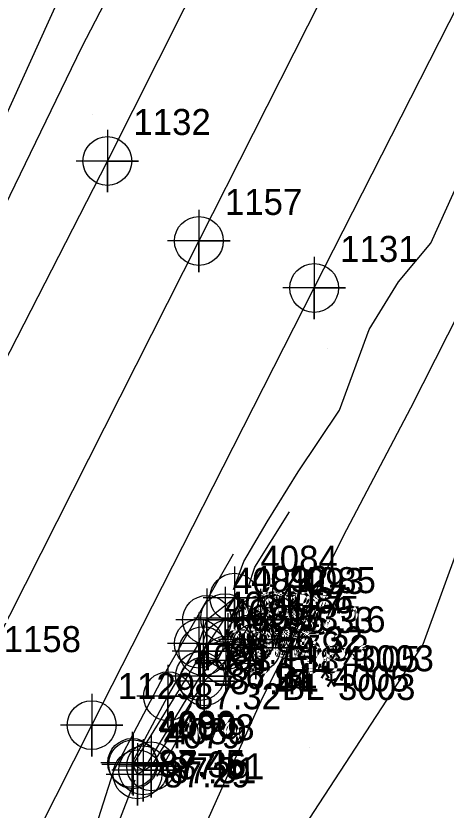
# Model space of a CAD drawing. Extents: x 2062781 to 2066835, y 358981 to 366501.
# Drawn here: x 2064085.2 to 2064126.5, y 361471.1 to 361547.4 of the extents above; entities that cross this region are included whole.
import ezdxf

# ---------------------------------------------------------------- set-up
doc = ezdxf.new("R2010")
doc.units = 0
for name, color, linetype in [('Exist DTM Breakline', 7, 'Continuous'), ('Exist DTM Breakline Cogo Comment', 7, 'Continuous'), ('Exist DTM Breakline Cogo Elevation', 7, 'Continuous'), ('Exist DTM Breakline Cogo Number', 7, 'Continuous'), ('Exist DTM Breakline Cogo Point CELL', 7, 'Continuous'), ('Exist DTM Crownline', 7, 'Continuous'), ('Exist DTM Crownline Cogo Number', 7, 'Continuous'), ('Exist DTM Crownline Cogo Point CELL', 7, 'Continuous'), ('Exist Roads EOP', 7, 'Continuous'), ('Exist Roads EOP Cogo Number', 7, 'Continuous'), ('Exist Roads EOP Cogo Point CELL', 7, 'Continuous'), ('Exist Roads EOP Other', 7, 'Continuous'), ('Exist Roads EOP Other Cogo Comment', 7, 'Continuous'), ('Exist Roads EOP Other Cogo Elevation', 7, 'Continuous'), ('Exist Roads EOP Other Cogo Number', 7, 'Continuous'), ('Exist Roads EOP Other Cogo Point CELL', 7, 'Continuous'), ('PH Exist DTM Breakline', 7, 'Continuous'), ('PH Exist DTM Point', 7, 'Continuous')]:
    doc.layers.add(name, color=color, linetype=linetype)

msp = doc.modelspace()

# ---------------------------------------------------------------- linework, layer by layer
at = {"layer": 'Exist DTM Breakline'}
msp.add_lwpolyline([(2064107.664, 361487.481), (2064105.549, 361487.003), (2064102.879, 361483.967), (2064097.416, 361474.92), (2064096.448, 361475.487), (2064103.189, 361486.361), (2064105.283, 361489.536), (2064108.699, 361489.355)], dxfattribs=at)
at = {"layer": 'Exist DTM Breakline Cogo Point CELL'}
for points in [[(2064105.283, 361492.536), (2064105.283, 361486.536), (2064105.283, 361489.536), (2064108.283, 361489.536), (2064102.283, 361489.536)], [(2064105.283, 361492.536), (2064105.283, 361486.536), (2064105.283, 361489.536), (2064108.283, 361489.536), (2064102.283, 361489.536)], [(2064105.283, 361492.536), (2064105.283, 361486.536), (2064105.283, 361489.536), (2064108.283, 361489.536), (2064102.283, 361489.536)], [(2064108.699, 361492.355), (2064108.699, 361486.355), (2064108.699, 361489.355), (2064111.699, 361489.355), (2064105.699, 361489.355)], [(2064108.699, 361492.355), (2064108.699, 361486.355), (2064108.699, 361489.355), (2064111.699, 361489.355), (2064105.699, 361489.355)], [(2064108.699, 361492.355), (2064108.699, 361486.355), (2064108.699, 361489.355), (2064111.699, 361489.355), (2064105.699, 361489.355)], [(2064105.549, 361490.003), (2064105.549, 361484.003), (2064105.549, 361487.003), (2064108.549, 361487.003), (2064102.549, 361487.003)], [(2064105.549, 361490.003), (2064105.549, 361484.003), (2064105.549, 361487.003), (2064108.549, 361487.003), (2064102.549, 361487.003)], [(2064105.549, 361490.003), (2064105.549, 361484.003), (2064105.549, 361487.003), (2064108.549, 361487.003), (2064102.549, 361487.003)], [(2064107.664, 361490.481), (2064107.664, 361484.481), (2064107.664, 361487.481), (2064110.664, 361487.481), (2064104.664, 361487.481)], [(2064107.664, 361490.481), (2064107.664, 361484.481), (2064107.664, 361487.481), (2064110.664, 361487.481), (2064104.664, 361487.481)], [(2064107.664, 361490.481), (2064107.664, 361484.481), (2064107.664, 361487.481), (2064110.664, 361487.481), (2064104.664, 361487.481)], [(2064103.189, 361489.361), (2064103.189, 361483.361), (2064103.189, 361486.361), (2064106.189, 361486.361), (2064100.189, 361486.361)], [(2064103.189, 361489.361), (2064103.189, 361483.361), (2064103.189, 361486.361), (2064106.189, 361486.361), (2064100.189, 361486.361)], [(2064103.189, 361489.361), (2064103.189, 361483.361), (2064103.189, 361486.361), (2064106.189, 361486.361), (2064100.189, 361486.361)], [(2064102.879, 361486.967), (2064102.879, 361480.967), (2064102.879, 361483.967), (2064105.879, 361483.967), (2064099.879, 361483.967)], [(2064102.879, 361486.967), (2064102.879, 361480.967), (2064102.879, 361483.967), (2064105.879, 361483.967), (2064099.879, 361483.967)], [(2064102.879, 361486.967), (2064102.879, 361480.967), (2064102.879, 361483.967), (2064105.879, 361483.967), (2064099.879, 361483.967)], [(2064096.448, 361478.487), (2064096.448, 361472.487), (2064096.448, 361475.487), (2064099.448, 361475.487), (2064093.448, 361475.487)], [(2064096.448, 361478.487), (2064096.448, 361472.487), (2064096.448, 361475.487), (2064099.448, 361475.487), (2064093.448, 361475.487)], [(2064096.448, 361478.487), (2064096.448, 361472.487), (2064096.448, 361475.487), (2064099.448, 361475.487), (2064093.448, 361475.487)], [(2064097.416, 361477.92), (2064097.416, 361471.92), (2064097.416, 361474.92), (2064100.416, 361474.92), (2064094.416, 361474.92)], [(2064097.416, 361477.92), (2064097.416, 361471.92), (2064097.416, 361474.92), (2064100.416, 361474.92), (2064094.416, 361474.92)], [(2064097.416, 361477.92), (2064097.416, 361471.92), (2064097.416, 361474.92), (2064100.416, 361474.92), (2064094.416, 361474.92)]]:
    msp.add_lwpolyline(points, dxfattribs=at)
for centre in [(2064105.283, 361489.536), (2064105.283, 361489.536), (2064105.283, 361489.536), (2064108.699, 361489.355), (2064108.699, 361489.355), (2064108.699, 361489.355), (2064107.664, 361487.481), (2064107.664, 361487.481), (2064107.664, 361487.481), (2064105.549, 361487.003), (2064105.549, 361487.003), (2064105.549, 361487.003), (2064103.189, 361486.361), (2064103.189, 361486.361), (2064103.189, 361486.361), (2064102.879, 361483.967), (2064102.879, 361483.967), (2064102.879, 361483.967), (2064096.448, 361475.487), (2064096.448, 361475.487), (2064096.448, 361475.487), (2064097.416, 361474.92), (2064097.416, 361474.92), (2064097.416, 361474.92)]:
    msp.add_circle(centre, 2.344, dxfattribs=at)
at = {"layer": 'Exist DTM Crownline'}
msp.add_lwpolyline([(2064265.441, 361845.695), (2064239.974, 361795.637), (2064213.324, 361743.862), (2064188.563, 361695.075), (2064163.474, 361645.604), (2064134.868, 361589.208), (2064123.648, 361567.027), (2064102.768, 361525.754), (2064081.502, 361483.764), (2064060.491, 361443.216), (2064039.785, 361402.117), (2064017.952, 361359.285), (2063998.021, 361320.112), (2063977.861, 361280.752), (2063957.656, 361241.435), (2063938.488, 361203.846), (2063917.61, 361163.02), (2063896.2, 361120.913), (2063873.972, 361077.232), (2063852.927, 361035.552), (2063832.77, 360995.688), (2063813.378, 360956.989), (2063791.843, 360915.199), (2063771.297, 360874.466)], dxfattribs=at)
at = {"layer": 'Exist DTM Crownline Cogo Point CELL'}
msp.add_lwpolyline([(2064102.768, 361528.754), (2064102.768, 361522.754), (2064102.768, 361525.754), (2064105.768, 361525.754), (2064099.768, 361525.754)], dxfattribs=at)
msp.add_lwpolyline([(2064102.768, 361528.754), (2064102.768, 361522.754), (2064102.768, 361525.754), (2064105.768, 361525.754), (2064099.768, 361525.754)], dxfattribs=at)
msp.add_lwpolyline([(2064102.768, 361528.754), (2064102.768, 361522.754), (2064102.768, 361525.754), (2064105.768, 361525.754), (2064099.768, 361525.754)], dxfattribs=at)
msp.add_circle((2064102.768, 361525.754), 2.344, dxfattribs=at)
msp.add_circle((2064102.768, 361525.754), 2.344, dxfattribs=at)
msp.add_circle((2064102.768, 361525.754), 2.344, dxfattribs=at)
at = {"layer": 'Exist Roads EOP'}
for points in [[(2063947.544, 361247.655), (2063967.277, 361286.12), (2063986.626, 361323.879), (2064008.237, 361366.151), (2064030.201, 361409.405), (2064050.535, 361448.686), (2064070.623, 361487.87), (2064093.973, 361533.433), (2064113.626, 361572.45), (2064134.872, 361614.055), (2064156.049, 361655.626), (2064176.927, 361697.028), (2064198.396, 361739.791), (2064219.665, 361781.226), (2064239.904, 361821.078), (2064255.886, 361852.537)], [(2063968.74, 361236.858), (2063988.59, 361275.837), (2064007.944, 361313.553), (2064029.338, 361355.45), (2064050.744, 361397.355), (2064071.707, 361438.157), (2064092.469, 361479.256), (2064113.842, 361521.244), (2064134.238, 361561.364), (2064154.674, 361602.171), (2064176.641, 361645.096), (2064197.635, 361686.254), (2064219.165, 361728.913), (2064239.98, 361769.728), (2064260.768, 361810.546), (2064276.589, 361841.965)]]:
    msp.add_lwpolyline(points, dxfattribs=at)
at = {"layer": 'Exist Roads EOP Cogo Point CELL'}
for points in [[(2064093.973, 361536.433), (2064093.973, 361530.433), (2064093.973, 361533.433), (2064096.973, 361533.433), (2064090.973, 361533.433)], [(2064093.973, 361536.433), (2064093.973, 361530.433), (2064093.973, 361533.433), (2064096.973, 361533.433), (2064090.973, 361533.433)], [(2064093.973, 361536.433), (2064093.973, 361530.433), (2064093.973, 361533.433), (2064096.973, 361533.433), (2064090.973, 361533.433)], [(2064113.842, 361524.244), (2064113.842, 361518.244), (2064113.842, 361521.244), (2064116.842, 361521.244), (2064110.842, 361521.244)], [(2064113.842, 361524.244), (2064113.842, 361518.244), (2064113.842, 361521.244), (2064116.842, 361521.244), (2064110.842, 361521.244)], [(2064113.842, 361524.244), (2064113.842, 361518.244), (2064113.842, 361521.244), (2064116.842, 361521.244), (2064110.842, 361521.244)], [(2064092.469, 361482.256), (2064092.469, 361476.256), (2064092.469, 361479.256), (2064095.469, 361479.256), (2064089.469, 361479.256)], [(2064092.469, 361482.256), (2064092.469, 361476.256), (2064092.469, 361479.256), (2064095.469, 361479.256), (2064089.469, 361479.256)], [(2064092.469, 361482.256), (2064092.469, 361476.256), (2064092.469, 361479.256), (2064095.469, 361479.256), (2064089.469, 361479.256)]]:
    msp.add_lwpolyline(points, dxfattribs=at)
for centre in [(2064093.973, 361533.433), (2064093.973, 361533.433), (2064093.973, 361533.433), (2064113.842, 361521.244), (2064113.842, 361521.244), (2064113.842, 361521.244), (2064092.469, 361479.256), (2064092.469, 361479.256), (2064092.469, 361479.256)]:
    msp.add_circle(centre, 2.344, dxfattribs=at)
at = {"layer": 'Exist Roads EOP Other'}
for points in [[(2064108.245, 361486.665), (2064105.372, 361485.459), (2064103.262, 361483.465), (2064098.18, 361475.305), (2064096.868, 361474.523), (2064096.358, 361475.627), (2064099.797, 361482.031), (2064102.764, 361487.082), (2064103.543, 361489.364), (2064106.177, 361491.493), (2064109.835, 361489.427), (2064108.245, 361486.665)], [(2064102.764, 361487.082), (2064103.543, 361489.364)]]:
    msp.add_lwpolyline(points, dxfattribs=at)
at = {"layer": 'Exist Roads EOP Other Cogo Point CELL'}
for points in [[(2064106.177, 361494.493), (2064106.177, 361488.493), (2064106.177, 361491.493), (2064109.177, 361491.493), (2064103.177, 361491.493)], [(2064106.177, 361494.493), (2064106.177, 361488.493), (2064106.177, 361491.493), (2064109.177, 361491.493), (2064103.177, 361491.493)], [(2064106.177, 361494.493), (2064106.177, 361488.493), (2064106.177, 361491.493), (2064109.177, 361491.493), (2064103.177, 361491.493)], [(2064103.543, 361492.364), (2064103.543, 361486.364), (2064103.543, 361489.364), (2064106.543, 361489.364), (2064100.543, 361489.364)], [(2064103.543, 361492.364), (2064103.543, 361486.364), (2064103.543, 361489.364), (2064106.543, 361489.364), (2064100.543, 361489.364)], [(2064103.543, 361492.364), (2064103.543, 361486.364), (2064103.543, 361489.364), (2064106.543, 361489.364), (2064100.543, 361489.364)], [(2064109.835, 361492.427), (2064109.835, 361486.427), (2064109.835, 361489.427), (2064112.835, 361489.427), (2064106.835, 361489.427)], [(2064109.835, 361492.427), (2064109.835, 361486.427), (2064109.835, 361489.427), (2064112.835, 361489.427), (2064106.835, 361489.427)], [(2064109.835, 361492.427), (2064109.835, 361486.427), (2064109.835, 361489.427), (2064112.835, 361489.427), (2064106.835, 361489.427)], [(2064102.764, 361490.082), (2064102.764, 361484.082), (2064102.764, 361487.082), (2064105.764, 361487.082), (2064099.764, 361487.082)], [(2064102.764, 361490.082), (2064102.764, 361484.082), (2064102.764, 361487.082), (2064105.764, 361487.082), (2064099.764, 361487.082)], [(2064102.764, 361490.082), (2064102.764, 361484.082), (2064102.764, 361487.082), (2064105.764, 361487.082), (2064099.764, 361487.082)], [(2064108.245, 361489.665), (2064108.245, 361483.665), (2064108.245, 361486.665), (2064111.245, 361486.665), (2064105.245, 361486.665)], [(2064108.245, 361489.665), (2064108.245, 361483.665), (2064108.245, 361486.665), (2064111.245, 361486.665), (2064105.245, 361486.665)], [(2064108.245, 361489.665), (2064108.245, 361483.665), (2064108.245, 361486.665), (2064111.245, 361486.665), (2064105.245, 361486.665)], [(2064105.372, 361488.459), (2064105.372, 361482.459), (2064105.372, 361485.459), (2064108.372, 361485.459), (2064102.372, 361485.459)], [(2064105.372, 361488.459), (2064105.372, 361482.459), (2064105.372, 361485.459), (2064108.372, 361485.459), (2064102.372, 361485.459)], [(2064105.372, 361488.459), (2064105.372, 361482.459), (2064105.372, 361485.459), (2064108.372, 361485.459), (2064102.372, 361485.459)], [(2064103.262, 361486.465), (2064103.262, 361480.465), (2064103.262, 361483.465), (2064106.262, 361483.465), (2064100.262, 361483.465)], [(2064103.262, 361486.465), (2064103.262, 361480.465), (2064103.262, 361483.465), (2064106.262, 361483.465), (2064100.262, 361483.465)], [(2064103.262, 361486.465), (2064103.262, 361480.465), (2064103.262, 361483.465), (2064106.262, 361483.465), (2064100.262, 361483.465)], [(2064099.797, 361485.031), (2064099.797, 361479.031), (2064099.797, 361482.031), (2064102.797, 361482.031), (2064096.797, 361482.031)], [(2064099.797, 361485.031), (2064099.797, 361479.031), (2064099.797, 361482.031), (2064102.797, 361482.031), (2064096.797, 361482.031)], [(2064099.797, 361485.031), (2064099.797, 361479.031), (2064099.797, 361482.031), (2064102.797, 361482.031), (2064096.797, 361482.031)], [(2064096.358, 361478.627), (2064096.358, 361472.627), (2064096.358, 361475.627), (2064099.358, 361475.627), (2064093.358, 361475.627)], [(2064096.358, 361478.627), (2064096.358, 361472.627), (2064096.358, 361475.627), (2064099.358, 361475.627), (2064093.358, 361475.627)], [(2064096.358, 361478.627), (2064096.358, 361472.627), (2064096.358, 361475.627), (2064099.358, 361475.627), (2064093.358, 361475.627)], [(2064098.18, 361478.305), (2064098.18, 361472.305), (2064098.18, 361475.305), (2064101.18, 361475.305), (2064095.18, 361475.305)], [(2064098.18, 361478.305), (2064098.18, 361472.305), (2064098.18, 361475.305), (2064101.18, 361475.305), (2064095.18, 361475.305)], [(2064098.18, 361478.305), (2064098.18, 361472.305), (2064098.18, 361475.305), (2064101.18, 361475.305), (2064095.18, 361475.305)], [(2064096.868, 361477.523), (2064096.868, 361471.523), (2064096.868, 361474.523), (2064099.868, 361474.523), (2064093.868, 361474.523)], [(2064096.868, 361477.523), (2064096.868, 361471.523), (2064096.868, 361474.523), (2064099.868, 361474.523), (2064093.868, 361474.523)], [(2064096.868, 361477.523), (2064096.868, 361471.523), (2064096.868, 361474.523), (2064099.868, 361474.523), (2064093.868, 361474.523)]]:
    msp.add_lwpolyline(points, dxfattribs=at)
for centre in [(2064106.177, 361491.493), (2064106.177, 361491.493), (2064106.177, 361491.493), (2064103.543, 361489.364), (2064103.543, 361489.364), (2064103.543, 361489.364), (2064109.835, 361489.427), (2064109.835, 361489.427), (2064109.835, 361489.427), (2064102.764, 361487.082), (2064102.764, 361487.082), (2064102.764, 361487.082), (2064108.245, 361486.665), (2064108.245, 361486.665), (2064108.245, 361486.665), (2064105.372, 361485.459), (2064105.372, 361485.459), (2064105.372, 361485.459), (2064103.262, 361483.465), (2064103.262, 361483.465), (2064103.262, 361483.465), (2064099.797, 361482.031), (2064099.797, 361482.031), (2064099.797, 361482.031), (2064096.358, 361475.627), (2064096.358, 361475.627), (2064096.358, 361475.627), (2064098.18, 361475.305), (2064098.18, 361475.305), (2064098.18, 361475.305), (2064096.868, 361474.523), (2064096.868, 361474.523), (2064096.868, 361474.523)]:
    msp.add_circle(centre, 2.344, dxfattribs=at)
at = {"layer": 'PH Exist DTM Breakline'}
for points in [[(2064157.636, 361670.668), (2064144.946, 361648.116), (2064132.684, 361625.091), (2064120.272, 361602.15), (2064104.593, 361569.587), (2064091.497, 361544.323), (2064076.204, 361512.861), (2064074.988, 361510.257), (2064073.823, 361508.184)], [(2064152.12, 361669.425), (2064135.907, 361639.637), (2064121.754, 361613.492), (2064110.383, 361589.099), (2064100.139, 361572.479), (2064090.136, 361550.895), (2064076.815, 361521.541), (2064074.014, 361513.479), (2064073.428, 361510.409)], [(2064190.717, 361645.188), (2064179.84, 361620.484), (2064168.688, 361597.509), (2064162.247, 361586.646), (2064154.244, 361570.703), (2064145.642, 361553.564), (2064136.409, 361535.169), (2064129.04, 361521.397), (2064123.089, 361509.693), (2064116.949, 361498.007), (2064108.836, 361481.844), (2064099.998, 361462.136)], [(2064106.091, 361492.289), (2064107.074, 361494.958), (2064109.329, 361498.79), (2064112.296, 361503.588), (2064116.283, 361509.502), (2064119.123, 361517.24), (2064121.938, 361521.834), (2064125.067, 361525.532), (2064130.12, 361536.715), (2064133.255, 361544.38), (2064136.917, 361551.323), (2064141.95, 361562.16), (2064146.471, 361572.133), (2064151.107, 361582.889), (2064154.904, 361591.52), (2064158.117, 361596.907), (2064163.177, 361605.617), (2064166.022, 361610.425)], [(2064169.73, 361588.421), (2064160.776, 361570.227), (2064152.848, 361554.43), (2064145.223, 361539.239), (2064135.861, 361520.588), (2064131.171, 361511.243), (2064128.874, 361501.931), (2064127.814, 361496.654), (2064124.292, 361486.999), (2064113.821, 361470.956), (2064105.667, 361458.423), (2064101.064, 361449.809), (2064096.582, 361440.88), (2064094.206, 361431.846), (2064089.171, 361420.333), (2064084.102, 361412.172), (2064081.203, 361402.724), (2064079.126, 361400.31), (2064075.785, 361398.219), (2064073.627, 361396.707), (2064071.474, 361392.468), (2064069.936, 361385.095), (2064071.015, 361378.419), (2064070.798, 361376.416)], [(2064107.531, 361492.561), (2064108.144, 361494.442), (2064111.458, 361499.727)], [(2064106.056, 361495.678), (2064099.707, 361484.632), (2064094.522, 361474.768), (2064093.091, 361470.243)], [(2064098.774, 361474.354), (2064101.671, 361479.568)], [(2064085.303, 361441.542), (2064089.393, 361455.015), (2064092.11, 361462), (2064095.409, 361470.754), (2064096.656, 361474.015)]]:
    msp.add_lwpolyline(points, dxfattribs=at)
at = {"layer": 'PH Exist DTM Point'}
for p, q in [((2064092.546, 361537.905), (2064092.546, 361537.905)), ((2064115.132, 361515.384), (2064115.132, 361515.384)), ((2064112.971, 361496.781), (2064112.971, 361496.781)), ((2064113.408, 361477.134), (2064113.408, 361477.134))]:
    msp.add_line(p, q, dxfattribs=at)

# ---------------------------------------------------------------- texts
at = {"layer": 'Exist DTM Breakline Cogo Comment'}
for s, p in [('EL*4005', (2064111.199, 361484.355)), ('EL*4005', (2064111.199, 361484.355)), ('EL*4005', (2064111.199, 361484.355)), ('BL*4005', (2064110.164, 361482.481)), ('BL*4005', (2064110.164, 361482.481)), ('BL*4005', (2064110.164, 361482.481))]:
    msp.add_text(s, height=2.5, dxfattribs=at).set_placement(p)
at = {"layer": 'Exist DTM Breakline Cogo Elevation'}
for s, p in [('86.53', (2064107.783, 361488.286)), ('86.53', (2064107.783, 361488.286)), ('86.53', (2064107.783, 361488.286)), ('86.33', (2064111.199, 361488.105)), ('86.33', (2064111.199, 361488.105)), ('86.33', (2064111.199, 361488.105)), ('86.32', (2064110.164, 361486.231)), ('86.32', (2064110.164, 361486.231)), ('86.32', (2064110.164, 361486.231)), ('86.74', (2064105.689, 361485.111)), ('86.74', (2064105.689, 361485.111)), ('86.74', (2064105.689, 361485.111)), ('86.59', (2064108.049, 361485.753)), ('86.59', (2064108.049, 361485.753)), ('86.59', (2064108.049, 361485.753)), ('86.94', (2064105.379, 361482.718)), ('86.94', (2064105.379, 361482.718)), ('86.94', (2064105.379, 361482.718)), ('87.36', (2064098.948, 361474.237)), ('87.36', (2064098.948, 361474.237)), ('87.36', (2064098.948, 361474.237)), ('87.31', (2064099.916, 361473.67)), ('87.31', (2064099.916, 361473.67)), ('87.31', (2064099.916, 361473.67))]:
    msp.add_text(s, height=2.5, dxfattribs=at).set_placement(p)
at = {"layer": 'Exist DTM Breakline Cogo Number'}
for s, p in [('4092', (2064107.783, 361492.036)), ('4092', (2064107.783, 361492.036)), ('4092', (2064107.783, 361492.036)), ('4093', (2064111.199, 361491.855)), ('4093', (2064111.199, 361491.855)), ('4093', (2064111.199, 361491.855)), ('4086', (2064110.164, 361489.981)), ('4086', (2064110.164, 361489.981)), ('4086', (2064110.164, 361489.981)), ('4091', (2064105.689, 361488.861)), ('4091', (2064105.689, 361488.861)), ('4091', (2064105.689, 361488.861)), ('4087', (2064108.049, 361489.503)), ('4087', (2064108.049, 361489.503)), ('4087', (2064108.049, 361489.503)), ('4088', (2064105.379, 361486.468)), ('4088', (2064105.379, 361486.468)), ('4088', (2064105.379, 361486.468)), ('4090', (2064098.948, 361477.987)), ('4090', (2064098.948, 361477.987)), ('4090', (2064098.948, 361477.987)), ('4089', (2064099.916, 361477.42)), ('4089', (2064099.916, 361477.42)), ('4089', (2064099.916, 361477.42))]:
    msp.add_text(s, height=2.5, dxfattribs=at).set_placement(p)
at = {"layer": 'Exist DTM Crownline Cogo Number'}
for s, p in [('1157', (2064105.268, 361528.254)), ('1157', (2064105.268, 361528.254)), ('1157', (2064105.268, 361528.254)), ('1158', (2064084.002, 361486.264)), ('1158', (2064084.002, 361486.264)), ('1158', (2064084.002, 361486.264))]:
    msp.add_text(s, height=2.5, dxfattribs=at).set_placement(p)
at = {"layer": 'Exist Roads EOP Cogo Number'}
for s, p in [('1132', (2064096.473, 361535.933)), ('1132', (2064096.473, 361535.933)), ('1132', (2064096.473, 361535.933)), ('1131', (2064116.342, 361523.744)), ('1131', (2064116.342, 361523.744)), ('1131', (2064116.342, 361523.744)), ('1129', (2064094.969, 361481.756)), ('1129', (2064094.969, 361481.756)), ('1129', (2064094.969, 361481.756))]:
    msp.add_text(s, height=2.5, dxfattribs=at).set_placement(p)
at = {"layer": 'Exist Roads EOP Other Cogo Comment'}
for s, p in [('CL*3003', (2064112.335, 361484.427)), ('CL*3003', (2064112.335, 361484.427)), ('CL*3003', (2064112.335, 361484.427)), ('BL*3003', (2064110.745, 361481.665)), ('BL*3003', (2064110.745, 361481.665)), ('BL*3003', (2064110.745, 361481.665))]:
    msp.add_text(s, height=2.5, dxfattribs=at).set_placement(p)
at = {"layer": 'Exist Roads EOP Other Cogo Elevation'}
for s, p in [('86.97', (2064108.677, 361490.243)), ('86.97', (2064108.677, 361490.243)), ('86.97', (2064108.677, 361490.243)), ('87.14', (2064106.043, 361488.115)), ('87.14', (2064106.043, 361488.115)), ('87.14', (2064106.043, 361488.115)), ('87.16', (2064112.335, 361488.177)), ('87.16', (2064112.335, 361488.177)), ('87.16', (2064112.335, 361488.177)), ('87.13', (2064105.264, 361485.832)), ('87.13', (2064105.264, 361485.832)), ('87.13', (2064105.264, 361485.832)), ('87.33', (2064110.745, 361485.415)), ('87.33', (2064110.745, 361485.415)), ('87.33', (2064110.745, 361485.415)), ('87.38', (2064107.872, 361484.209)), ('87.38', (2064107.872, 361484.209)), ('87.38', (2064107.872, 361484.209)), ('87.44', (2064105.762, 361482.215)), ('87.44', (2064105.762, 361482.215)), ('87.44', (2064105.762, 361482.215)), ('87.32', (2064102.297, 361480.781)), ('87.32', (2064102.297, 361480.781)), ('87.32', (2064102.297, 361480.781)), ('87.45', (2064098.858, 361474.377)), ('87.45', (2064098.858, 361474.377)), ('87.45', (2064098.858, 361474.377)), ('87.51', (2064100.68, 361474.055)), ('87.51', (2064100.68, 361474.055)), ('87.51', (2064100.68, 361474.055)), ('87.29', (2064099.368, 361473.273)), ('87.29', (2064099.368, 361473.273)), ('87.29', (2064099.368, 361473.273))]:
    msp.add_text(s, height=2.5, dxfattribs=at).set_placement(p)
at = {"layer": 'Exist Roads EOP Other Cogo Number'}
for s, p in [('4084', (2064108.677, 361493.993)), ('4084', (2064108.677, 361493.993)), ('4084', (2064108.677, 361493.993)), ('4083', (2064106.043, 361491.865)), ('4083', (2064106.043, 361491.865)), ('4083', (2064106.043, 361491.865)), ('4085', (2064112.335, 361491.927)), ('4085', (2064112.335, 361491.927)), ('4085', (2064112.335, 361491.927)), ('4082', (2064105.264, 361489.582)), ('4082', (2064105.264, 361489.582)), ('4082', (2064105.264, 361489.582)), ('4075', (2064110.745, 361489.165)), ('4075', (2064110.745, 361489.165)), ('4075', (2064110.745, 361489.165)), ('4076', (2064107.872, 361487.959)), ('4076', (2064107.872, 361487.959)), ('4076', (2064107.872, 361487.959)), ('4077', (2064105.762, 361485.965)), ('4077', (2064105.762, 361485.965)), ('4077', (2064105.762, 361485.965)), ('4081', (2064102.297, 361484.531)), ('4081', (2064102.297, 361484.531)), ('4081', (2064102.297, 361484.531)), ('4080', (2064098.858, 361478.127)), ('4080', (2064098.858, 361478.127)), ('4080', (2064098.858, 361478.127)), ('4078', (2064100.68, 361477.805)), ('4078', (2064100.68, 361477.805)), ('4078', (2064100.68, 361477.805)), ('4079', (2064099.368, 361477.023)), ('4079', (2064099.368, 361477.023)), ('4079', (2064099.368, 361477.023))]:
    msp.add_text(s, height=2.5, dxfattribs=at).set_placement(p)

doc.saveas('drawing.dxf')
